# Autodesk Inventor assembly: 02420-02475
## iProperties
Author: Administrator
Shininess: 64.0
Angle Display Precision: 2
Document Length Units: 11272
Document Angle Units: 11286
Document Time Units: 11279
Document Mass Units: 11290
Document Length Units Precision: 3
Document Angle Units Precision: 2
Compacted: True
PropertySet Name: _Private Model Information
Created: 2002-04
Part Number: 02420-02475
Document SubType Name: Assembly
Designer: Administrator
Control State: 0
Master: False
Checked Out: False
PropertySet Name: Design Tracking Control
Density: 0.0
Volumn: 0.0
Area: 0.0
PropertySet Name: Model Information
